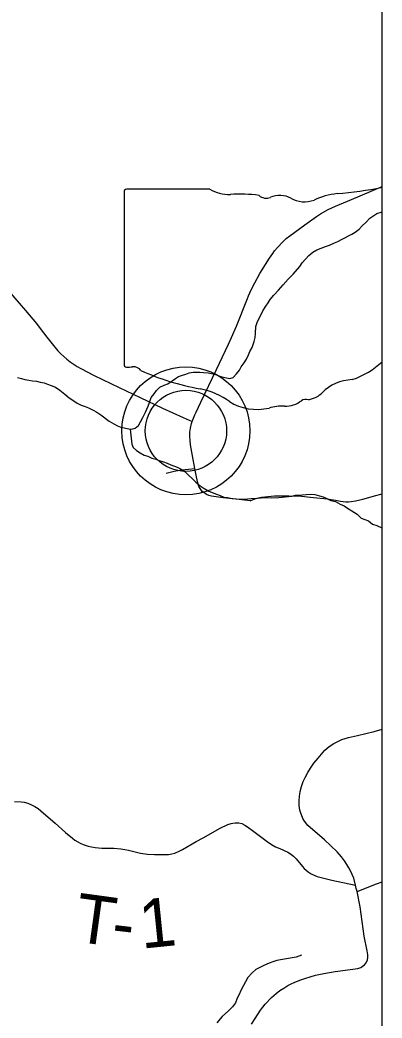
# Model space of a CAD drawing. Extents: x 0 to 191, y 0 to 55.
# Drawn here: x 190.549 to 190.97, y 50.382 to 51.542 of the extents above; entities that cross this region are included whole.
import ezdxf

# ---------------------------------------------------------------- set-up
doc = ezdxf.new("R2010")
doc.units = 0
for name, color, linetype in [('Default', 7, 'Continuous'), ('GM_X_Corporation', 7, 'Continuous'), ('GM_X_County_Road', 7, 'Continuous'), ('GM_X_Minor_River', 7, 'Continuous'), ('GM_X_State_Location', 7, 'Continuous'), ('GM_X_State_Route', 7, 'Continuous'), ('GM_X_Township_Road', 7, 'Continuous'), ('GM_X_Township_Road_Text', 7, 'Continuous'), ('GM_X_Unincorporated', 7, 'Continuous'), ('GM_X_Unincorporated_Location', 7, 'Continuous')]:
    doc.layers.add(name, color=color, linetype=linetype)

msp = doc.modelspace()

# ---------------------------------------------------------------- linework, layer by layer
at = {"layer": 'Default'}
for p, q in [((190.9701, 51.1447), (190.9701, 51.3476)), ((190.6703, 51.342), (190.6703, 51.142)), ((190.7701, 51.3455), (190.6735, 51.3455))]:
    msp.add_line(p, q, dxfattribs=at)
for centre, major_axis, start_param, end_param in [((190.8825, 51.6183), (0.3495, 0), 4.814394, 4.965624), ((190.6741, 51.3425), (0.00382, 0), 1.727492, 3.291633), ((190.7931, 51.3687), (0.037, 0), 4.042888, 4.731792), ((190.8053, 51.2332), (0.133, 0), 1.404758, 1.657859), ((190.8355, 51.3435), (0.0107, 0), 3.836095, 5.185415), ((190.8512, 51.3204), (0.0222, 0), 0.950623, 2.079405), ((190.8799, 51.3521), (0.0267, 0), 4.08156, 5.145723), ((190.9271, 51.2844), (0.0703, 0), 1.699012, 2.107814), ((190.6741, 51.1415), (0.00385, 0), 2.993084, 4.5083), ((190.6747, 51.162), (0.0294, 0), 4.665946, 4.897461), ((190.6807, 51.1304), (0.0106, 0), 0.519207, 1.627899), ((190.9021, 51.1887), (0.0874, 0), 5.101753, 5.603373), ((190.8145, 51.3102), (0.2524, 0), 4.195997, 4.488961), ((190.9389, 51.0858), (0.0479, 0), 1.647645, 2.488434), ((190.7393, 51.052), (0.079, 0), 0.823519, 1.323587), ((190.8783, 51.1226), (0.0282, 0), 4.937069, 5.64225), ((190.8247, 51.1294), (0.0501, 0), 4.026481, 4.996735), ((190.8537, 51.0602), (0.0412, 0), 1.495662, 1.94098), ((190.8573, 51.1144), (0.0267, 0), 4.691044, 5.507374), ((190.8815, 51.095), (0.00752, 0), 1.147584, 2.315152)]:
    msp.add_ellipse(centre, major_axis=major_axis, ratio=0.8, start_param=start_param, end_param=end_param, dxfattribs=at)
at = {"layer": 'GM_X_Corporation'}
for points in [[(190.9701, 48.3247), (190.9701, 54.7197), (190.454, 54.7197), (190.4414, 54.232), (190.4414, 54.2285), (190.4406, 54.1842), (190.439, 54.0815), (190.4424, 53.938), (190.4402, 53.9289), (190.4381, 53.8288), (190.4278, 53.4957), (190.4249, 53.313), (190.4236, 53.2062), (190.4004, 52.3955), (190.3936, 51.6386), (190.3866, 51.3672), (190.3751, 50.4761), (190.3641, 48.8031), (190.3574, 48.3286), (190.6516, 48.3257)], [(190.9701, 48.3247), (190.9701, 54.2263), (190.9346, 54.2267), (190.5853, 54.2302), (190.4756, 54.2313), (190.4414, 54.232), (190.4414, 54.2285), (190.4406, 54.1842), (190.439, 54.0815), (190.4424, 53.938), (190.4402, 53.9289), (190.4381, 53.8288), (190.4278, 53.4957), (190.4249, 53.313), (190.4236, 53.2062), (190.4004, 52.3955), (190.3936, 51.6386), (190.3866, 51.3672), (190.3751, 50.4761), (190.3641, 48.8031), (190.3574, 48.3286), (190.6516, 48.3257)]]:
    msp.add_lwpolyline(points, close=True, dxfattribs=at)
at = {"layer": 'GM_X_County_Road'}
for points in [[(190.3868, 51.3666), (190.3929, 51.3622), (190.4042, 51.3529), (190.4241, 51.3367), (190.4392, 51.3233), (190.4664, 51.3009), (190.485, 51.2852), (190.4937, 51.2773), (190.4991, 51.2715), (190.5036, 51.2664), (190.5242, 51.2416), (190.5362, 51.227), (190.5558, 51.2043), (190.5684, 51.1891), (190.5728, 51.1835), (190.5805, 51.1734)], [(190.5805, 51.1734), (190.582, 51.1715), (190.5883, 51.1636), (190.5935, 51.1574), (190.5969, 51.1539), (190.6039, 51.1477), (190.6078, 51.1447), (190.6123, 51.1416), (190.616, 51.1393), (190.6202, 51.1369), (190.6355, 51.1289), (190.6647, 51.1149), (190.6891, 51.1033), (190.7151, 51.0906), (190.7389, 51.0798), (190.7495, 51.0754)]]:
    msp.add_lwpolyline(points, dxfattribs=at)
at = {"layer": 'GM_X_Minor_River'}
for points in [[(190.8124, 51.1479), (190.815, 51.1528), (190.8164, 51.1567), (190.819, 51.1612), (190.8215, 51.1681), (190.8226, 51.1731), (190.8229, 51.1776), (190.8235, 51.1856), (190.8249, 51.1902), (190.8315, 51.2039), (190.8352, 51.2093), (190.8378, 51.2131), (190.84, 51.217), (190.8444, 51.222), (190.8496, 51.2278), (190.8552, 51.2343), (190.8611, 51.2408), (190.8667, 51.2466), (190.8745, 51.2555), (190.8774, 51.2597), (190.8811, 51.2639), (190.8852, 51.2682), (190.8897, 51.2721), (190.8942, 51.2748), (190.8995, 51.2768), (190.9044, 51.2788), (190.9092, 51.2804), (190.9149, 51.2831), (190.9186, 51.2847), (190.9239, 51.2871), (190.9351, 51.293), (190.9389, 51.2953), (190.9434, 51.2988), (190.9471, 51.3026), (190.9515, 51.3069), (190.956, 51.3115), (190.9642, 51.317), (190.9691, 51.3186), (190.9701, 51.3189)], [(190.5464, 51.1265), (190.551, 51.1251), (190.5551, 51.124), (190.5597, 51.1233), (190.5639, 51.1226), (190.5684, 51.122), (190.573, 51.1209), (190.5775, 51.1202), (190.5813, 51.1188), (190.5855, 51.1173), (190.5905, 51.1151), (190.5958, 51.1118), (190.6016, 51.107), (190.6066, 51.1029), (190.6119, 51.0992), (190.6158, 51.0966), (190.6204, 51.0944), (190.6253, 51.0926), (190.6291, 51.0912), (190.6345, 51.0886), (190.6387, 51.086), (190.6433, 51.0831), (190.6532, 51.0757), (190.6586, 51.0724), (190.6628, 51.0702), (190.6666, 51.0687), (190.6757, 51.0666), (190.6795, 51.0663), (190.6833, 51.0675), (190.687, 51.0706), (190.6896, 51.0748), (190.6921, 51.0798), (190.6954, 51.0863), (190.6983, 51.0932), (190.6998, 51.0974), (190.7019, 51.1031), (190.7053, 51.1073), (190.7082, 51.1115), (190.7119, 51.115), (190.7168, 51.1174), (190.721, 51.119), (190.7262, 51.1225), (190.7299, 51.1252), (190.7337, 51.1275), (190.7382, 51.1291), (190.742, 51.1303), (190.7461, 51.1319), (190.7506, 51.1328), (190.7544, 51.1328), (190.7582, 51.1325), (190.7627, 51.1322), (190.768, 51.1319), (190.7718, 51.1312), (190.7756, 51.1302), (190.7794, 51.1287), (190.784, 51.1273), (190.7893, 51.1259), (190.7931, 51.1252), (190.7969, 51.1264), (190.801, 51.1306), (190.8043, 51.1348), (190.8065, 51.139), (190.8098, 51.1433), (190.8124, 51.1479)], [(190.6775, 51.0665), (190.6794, 51.0489), (190.681, 51.0451), (190.6848, 51.0417), (190.6891, 51.0388), (190.6936, 51.0362), (190.6978, 51.0348), (190.7024, 51.0326), (190.7073, 51.0315), (190.7111, 51.0301), (190.7161, 51.0283), (190.7203, 51.0268), (190.7245, 51.025), (190.7321, 51.0221), (190.7359, 51.0203), (190.7409, 51.0173), (190.7451, 51.0129), (190.7497, 51.0088), (190.7536, 51.0047), (190.7586, 51.0006), (190.7624, 50.998), (190.7689, 50.9943), (190.7777, 50.9907), (190.7819, 50.9892), (190.7864, 50.9874), (190.7906, 50.9871), (190.7959, 50.9857), (190.8008, 50.9854), (190.8046, 50.9851), (190.8137, 50.9853), (190.8175, 50.9857), (190.8254, 50.9862), (190.8296, 50.9867), (190.8368, 50.9868), (190.8421, 50.9865), (190.85, 50.987), (190.8651, 50.9884), (190.8696, 50.9897), (190.8772, 50.9902), (190.8821, 50.9906), (190.8874, 50.9907), (190.892, 50.9904), (190.8973, 50.989), (190.9015, 50.9876), (190.9053, 50.9861), (190.9106, 50.9835), (190.9159, 50.9821), (190.9213, 50.9792), (190.9259, 50.9774), (190.9301, 50.9744), (190.935, 50.9715), (190.9412, 50.9674), (190.9458, 50.9629), (190.9542, 50.9597), (190.9588, 50.956), (190.9641, 50.9542), (190.9698, 50.9516), (190.9701, 50.9515)], [(190.8766, 50.4549), (190.8703, 50.4525), (190.8544, 50.4499), (190.848, 50.4487), (190.8431, 50.4471), (190.839, 50.4455), (190.8326, 50.4427), (190.8236, 50.438), (190.8191, 50.4342), (190.8143, 50.4288), (190.8113, 50.4238), (190.8062, 50.4146), (190.8037, 50.4085), (190.8018, 50.4047), (190.7997, 50.3993), (190.7963, 50.3947), (190.7915, 50.3901), (190.7844, 50.3835), (190.7781, 50.3762)]]:
    msp.add_lwpolyline(points, dxfattribs=at)
at = {"layer": 'GM_X_State_Route'}
for p, q in [((190.9345, 51.3335), (190.9701, 51.3485)), ((190.8169, 50.983), (190.8071, 50.9841))]:
    msp.add_line(p, q, dxfattribs=at)
for points in [[(190.7495, 51.0754), (190.7527, 51.0831), (190.7542, 51.0863), (190.7596, 51.0978), (190.7779, 51.1356), (190.7918, 51.1652), (190.7953, 51.1731), (190.8009, 51.1863), (190.8137, 51.2182), (190.815, 51.2213), (190.8182, 51.2284), (190.8221, 51.2364), (190.8281, 51.2473), (190.8346, 51.2578), (190.8392, 51.265), (190.8431, 51.2707), (190.8453, 51.2736), (190.8485, 51.2774), (190.8547, 51.2842), (190.8588, 51.2879), (190.8628, 51.2911), (190.8802, 51.3038), (190.8941, 51.3137), (190.8985, 51.3166), (190.9074, 51.3216), (190.9161, 51.3258), (190.9345, 51.3335)], [(190.8071, 50.9841), (190.8042, 50.9844), (190.7854, 50.9866), (190.7719, 50.9886), (190.769, 50.9893), (190.7661, 50.9905), (190.7644, 50.9915), (190.7612, 50.9939), (190.7587, 50.9972), (190.7573, 50.9997), (190.7559, 51.0039), (190.7544, 51.0108), (190.7524, 51.0208), (190.7498, 51.0355), (190.7477, 51.048), (190.747, 51.053), (190.7468, 51.058), (190.7469, 51.0628), (190.7475, 51.0676), (190.7487, 51.0728), (190.7495, 51.0754)], [(190.8184, 50.3745), (190.826, 50.3867), (190.829, 50.391), (190.8343, 50.3978), (190.8415, 50.4056), (190.8472, 50.4104), (190.8515, 50.4137), (190.8559, 50.4166), (190.8606, 50.4194), (190.8645, 50.4214), (190.868, 50.423), (190.8747, 50.4257), (190.8815, 50.4281), (190.8867, 50.4298), (190.8929, 50.4315), (190.9024, 50.4337), (190.9157, 50.436), (190.9419, 50.4395), (190.9432, 50.4398), (190.9454, 50.4406), (190.9469, 50.4415), (190.9498, 50.4436), (190.9516, 50.446), (190.953, 50.4493), (190.9535, 50.452), (190.9536, 50.4551), (190.9529, 50.4597), (190.9493, 50.4771), (190.9468, 50.4938), (190.9446, 50.511), (190.941, 50.5287), (190.9402, 50.5323), (190.9394, 50.5363), (190.9372, 50.5443), (190.9354, 50.5487), (190.9336, 50.5528), (190.9315, 50.5565), (190.9292, 50.5604), (190.9265, 50.5645), (190.9229, 50.5692), (190.9179, 50.5749), (190.9107, 50.5819), (190.9031, 50.5888), (190.884, 50.6054), (190.8801, 50.6106), (190.8781, 50.6139), (190.8763, 50.6179), (190.8756, 50.62), (190.8747, 50.6235), (190.8739, 50.6287), (190.8737, 50.6343), (190.8741, 50.6397), (190.8745, 50.6421), (190.875, 50.6451), (190.8766, 50.6511), (190.8786, 50.6568), (190.8807, 50.6614), (190.8837, 50.6671), (190.887, 50.6724), (190.8909, 50.678), (190.8958, 50.684), (190.9036, 50.693), (190.9088, 50.6973), (190.914, 50.7009), (190.9186, 50.7034), (190.9235, 50.7055), (190.9273, 50.7068), (190.9312, 50.7079), (190.9414, 50.7104), (190.9608, 50.7148), (190.9701, 50.7174)]]:
    msp.add_lwpolyline(points, dxfattribs=at)
at = {"layer": 'GM_X_Township_Road'}
for points in [[(190.7192, 51.0152), (190.7284, 51.0176), (190.7369, 51.0189), (190.7452, 51.0199), (190.7524, 51.0208)], [(190.8169, 50.983), (190.8224, 50.9852), (190.8264, 50.9865), (190.8299, 50.9873), (190.8374, 50.9882), (190.8452, 50.9887), (190.8519, 50.9888), (190.8617, 50.9888), (190.8764, 50.9883), (190.8904, 50.9871), (190.9062, 50.9854), (190.9161, 50.9837), (190.9217, 50.9827), (190.925, 50.9821), (190.9281, 50.9819), (190.931, 50.982), (190.9343, 50.9823), (190.9392, 50.9831), (190.9476, 50.985), (190.963, 50.9892), (190.9686, 50.9907), (190.9701, 50.991)], [(190.543, 50.6335), (190.5507, 50.6332), (190.5541, 50.6326), (190.5585, 50.6315), (190.5627, 50.6298), (190.5668, 50.6278), (190.5706, 50.6254), (190.5738, 50.6228), (190.5903, 50.6083), (190.6021, 50.5976), (190.6106, 50.5908), (190.6133, 50.5887), (190.6166, 50.5866), (190.6193, 50.5851), (190.6229, 50.5834), (190.6288, 50.5815), (190.6326, 50.5806), (190.6366, 50.5799), (190.6406, 50.5795), (190.6446, 50.5793), (190.6586, 50.5791), (190.6665, 50.5785), (190.6712, 50.5778), (190.6755, 50.577), (190.6895, 50.5735), (190.692, 50.573), (190.6976, 50.5722), (190.7057, 50.5717), (190.722, 50.5718), (190.7259, 50.5725), (190.7294, 50.5734), (190.7345, 50.5756), (190.7384, 50.5776), (190.7542, 50.5868), (190.7621, 50.5913), (190.782, 50.6025), (190.7909, 50.6067), (190.7946, 50.608), (190.7966, 50.6084), (190.7995, 50.6087), (190.8035, 50.6085), (190.8071, 50.6078), (190.8105, 50.6061), (190.8137, 50.604), (190.8211, 50.5987), (190.8367, 50.5868), (190.8416, 50.5834), (190.8464, 50.5808), (190.8513, 50.5788), (190.8605, 50.5746), (190.8637, 50.5726), (190.8672, 50.5698), (190.8702, 50.5667), (190.8776, 50.5578), (190.8797, 50.5555), (190.8842, 50.5517), (190.8879, 50.5493), (190.8918, 50.5474), (190.8948, 50.5463), (190.8979, 50.5454), (190.9117, 50.5422), (190.9394, 50.5363)], [(190.941, 50.5287), (190.9635, 50.5376), (190.9701, 50.54)]]:
    msp.add_lwpolyline(points, dxfattribs=at)
at = {"layer": 'GM_X_Unincorporated'}
for radius in [0.0744, 0.0472]:
    msp.add_circle((190.7422, 51.0644), radius, dxfattribs=at)
at = {"layer": 'GM_X_Unincorporated_Location'}
msp.add_line((190.7422, 51.0644), (190.7422, 51.0644), dxfattribs=at)

# ---------------------------------------------------------------- texts
at = {"layer": 'GM_X_State_Location'}
for s in ['s', 'r']:
    msp.add_text(s, height=0.000189, dxfattribs=at).set_placement((190.8314, 51.2287))
msp.add_text('379', height=0.000189, rotation=0, dxfattribs=at).set_placement((190.7645, 51.2149))
at = {"layer": 'GM_X_Township_Road_Text'}
for s, rotation, p in [('T', 352.1563, (190.6109, 50.4711)), ('1', 5.7931, (190.6908, 50.4623)), ('-', 353.2577, (190.6542, 50.4652))]:
    msp.add_text(s, height=0.0568, rotation=rotation, dxfattribs=at).set_placement(p)

doc.saveas('drawing.dxf')
